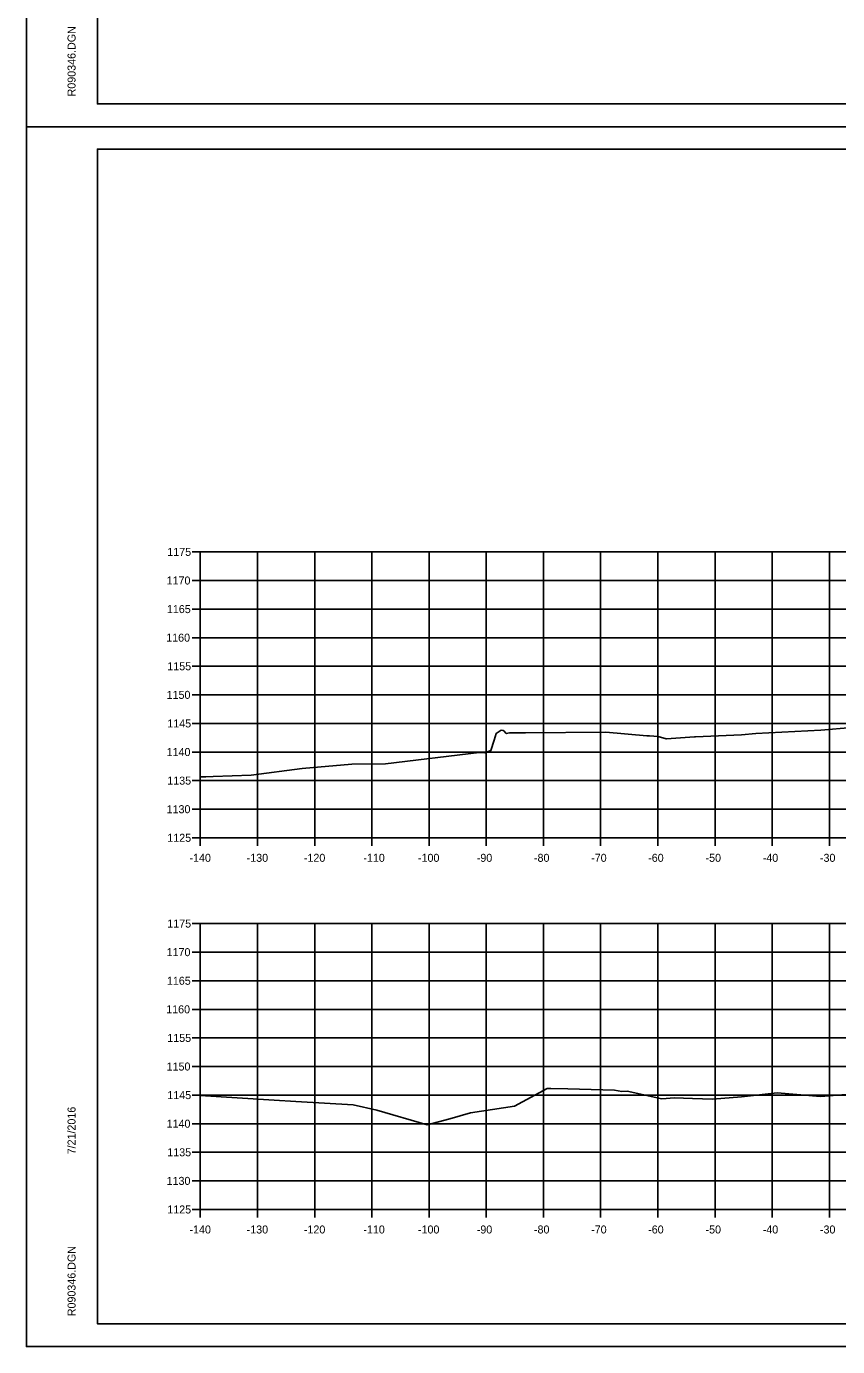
# Model space of a CAD drawing. Extents: x 1368971 to 1374497, y 378717 to 381839.
# Drawn here: x 1371092.2 to 1371234.1, y 381199.4 to 381430.3 of the extents above; entities that cross this region are included whole.
import ezdxf

# ---------------------------------------------------------------- set-up
doc = ezdxf.new("R2010")
doc.units = 0
for name, color, linetype in [('R_Axis', 7, 'Continuous'), ('R_Axis Annot', 7, 'Continuous'), ('R_Exist Surface', 7, 'Continuous'), ('R_Grid', 7, 'Continuous'), ('R_No Plot', 7, 'Continuous')]:
    doc.layers.add(name, color=color, linetype=linetype)

msp = doc.modelspace()

# ---------------------------------------------------------------- linework, layer by layer
at = {"layer": 'R_Axis'}
for p, q in [((1371121.24, 381338.41), (1371122.64, 381338.41)), ((1371122.64, 381288.41), (1371122.64, 381338.41)), ((1371121.24, 381333.41), (1371122.64, 381333.41)), ((1371121.24, 381328.41), (1371122.64, 381328.41)), ((1371121.24, 381323.41), (1371122.64, 381323.41)), ((1371121.24, 381318.41), (1371122.64, 381318.41)), ((1371121.24, 381313.41), (1371122.64, 381313.41)), ((1371121.24, 381308.41), (1371122.64, 381308.41)), ((1371121.24, 381303.41), (1371122.64, 381303.41)), ((1371121.24, 381298.41), (1371122.64, 381298.41)), ((1371121.24, 381293.41), (1371122.64, 381293.41)), ((1371121.24, 381288.41), (1371122.64, 381288.41)), ((1371122.64, 381288.41), (1371402.64, 381288.41)), ((1371122.64, 381287.01), (1371122.64, 381288.41)), ((1371132.64, 381287.01), (1371132.64, 381288.41)), ((1371142.64, 381287.01), (1371142.64, 381288.41)), ((1371152.64, 381287.01), (1371152.64, 381288.41)), ((1371162.64, 381287.01), (1371162.64, 381288.41)), ((1371172.64, 381287.01), (1371172.64, 381288.41)), ((1371182.64, 381287.01), (1371182.64, 381288.41)), ((1371192.64, 381287.01), (1371192.64, 381288.41)), ((1371202.64, 381287.01), (1371202.64, 381288.41)), ((1371212.64, 381287.01), (1371212.64, 381288.41)), ((1371222.64, 381287.01), (1371222.64, 381288.41)), ((1371232.64, 381287.01), (1371232.64, 381288.41)), ((1371121.24, 381273.41), (1371122.64, 381273.41)), ((1371122.64, 381223.41), (1371122.64, 381273.41)), ((1371121.24, 381268.41), (1371122.64, 381268.41)), ((1371121.24, 381263.41), (1371122.64, 381263.41)), ((1371121.24, 381258.41), (1371122.64, 381258.41)), ((1371121.24, 381253.41), (1371122.64, 381253.41)), ((1371121.24, 381248.41), (1371122.64, 381248.41)), ((1371121.24, 381243.41), (1371122.64, 381243.41)), ((1371121.24, 381238.41), (1371122.64, 381238.41)), ((1371121.24, 381233.41), (1371122.64, 381233.41)), ((1371121.24, 381228.41), (1371122.64, 381228.41)), ((1371121.24, 381223.41), (1371122.64, 381223.41)), ((1371122.64, 381223.41), (1371402.64, 381223.41)), ((1371122.64, 381222.01), (1371122.64, 381223.41)), ((1371132.64, 381222.01), (1371132.64, 381223.41)), ((1371142.64, 381222.01), (1371142.64, 381223.41)), ((1371152.64, 381222.01), (1371152.64, 381223.41)), ((1371162.64, 381222.01), (1371162.64, 381223.41)), ((1371172.64, 381222.01), (1371172.64, 381223.41)), ((1371182.64, 381222.01), (1371182.64, 381223.41)), ((1371192.64, 381222.01), (1371192.64, 381223.41)), ((1371202.64, 381222.01), (1371202.64, 381223.41)), ((1371212.64, 381222.01), (1371212.64, 381223.41)), ((1371222.64, 381222.01), (1371222.64, 381223.41)), ((1371232.64, 381222.01), (1371232.64, 381223.41))]:
    msp.add_line(p, q, dxfattribs=at)
at = {"layer": 'R_Exist Surface'}
for points in [[(1371122.64, 381299.05), (1371123.59, 381299.09), (1371124.87, 381299.14), (1371131.55, 381299.39), (1371140.46, 381300.53), (1371149.14, 381301.31), (1371155, 381301.33), (1371171.42, 381303.33), (1371172.41, 381303.28), (1371173.41, 381303.67), (1371174.04, 381305.49), (1371174.39, 381306.65), (1371175.22, 381307.26), (1371175.59, 381307.2), (1371175.7, 381307.11), (1371176.12, 381306.63), (1371176.71, 381306.76), (1371179.52, 381306.78), (1371193.57, 381306.87), (1371200.7, 381306.24), (1371201.2, 381306.23), (1371202.68, 381306.1), (1371204.07, 381305.69), (1371204.13, 381305.73), (1371209.05, 381306.07), (1371209.22, 381306.09), (1371217.24, 381306.42), (1371219.79, 381306.64), (1371231.16, 381307.24), (1371236.57, 381307.71)], [(1371122.64, 381243.36), (1371135.55, 381242.55), (1371139.35, 381242.27), (1371149.36, 381241.69), (1371153.48, 381240.77), (1371162.29, 381238.19), (1371166.24, 381239.29), (1371169.87, 381240.31), (1371177.6, 381241.45), (1371183.28, 381244.55), (1371183.93, 381244.57), (1371186.91, 381244.52), (1371195.05, 381244.28), (1371196.32, 381244.05), (1371197.26, 381244.08), (1371203.34, 381242.76), (1371205.55, 381242.93), (1371208.67, 381242.79), (1371212.17, 381242.71), (1371217.24, 381243.11), (1371223.51, 381243.79), (1371231.05, 381243.19), (1371235.54, 381243.53)]]:
    msp.add_lwpolyline(points, dxfattribs=at)
at = {"layer": 'R_Grid'}
for p, q in [((1371122.64, 381338.41), (1371402.64, 381338.41)), ((1371122.64, 381288.41), (1371122.64, 381338.41)), ((1371132.64, 381288.41), (1371132.64, 381338.41)), ((1371142.64, 381288.41), (1371142.64, 381338.41)), ((1371152.64, 381288.41), (1371152.64, 381338.41)), ((1371162.64, 381288.41), (1371162.64, 381338.41)), ((1371172.64, 381288.41), (1371172.64, 381338.41)), ((1371182.64, 381288.41), (1371182.64, 381338.41)), ((1371192.64, 381288.41), (1371192.64, 381338.41)), ((1371202.64, 381288.41), (1371202.64, 381338.41)), ((1371212.64, 381288.41), (1371212.64, 381338.41)), ((1371222.64, 381288.41), (1371222.64, 381338.41)), ((1371232.64, 381288.41), (1371232.64, 381338.41)), ((1371122.64, 381333.41), (1371402.64, 381333.41)), ((1371122.64, 381328.41), (1371402.64, 381328.41)), ((1371122.64, 381323.41), (1371402.64, 381323.41)), ((1371122.64, 381318.41), (1371402.64, 381318.41)), ((1371122.64, 381313.41), (1371402.64, 381313.41)), ((1371122.64, 381308.41), (1371402.64, 381308.41)), ((1371122.64, 381303.41), (1371402.64, 381303.41)), ((1371122.64, 381298.41), (1371402.64, 381298.41)), ((1371122.64, 381293.41), (1371402.64, 381293.41)), ((1371122.64, 381288.41), (1371402.64, 381288.41)), ((1371122.64, 381273.41), (1371402.64, 381273.41)), ((1371122.64, 381223.41), (1371122.64, 381273.41)), ((1371132.64, 381223.41), (1371132.64, 381273.41)), ((1371142.64, 381223.41), (1371142.64, 381273.41)), ((1371152.64, 381223.41), (1371152.64, 381273.41)), ((1371162.64, 381223.41), (1371162.64, 381273.41)), ((1371172.64, 381223.41), (1371172.64, 381273.41)), ((1371182.64, 381223.41), (1371182.64, 381273.41)), ((1371192.64, 381223.41), (1371192.64, 381273.41)), ((1371202.64, 381223.41), (1371202.64, 381273.41)), ((1371212.64, 381223.41), (1371212.64, 381273.41)), ((1371222.64, 381223.41), (1371222.64, 381273.41)), ((1371232.64, 381223.41), (1371232.64, 381273.41)), ((1371122.64, 381268.41), (1371402.64, 381268.41)), ((1371122.64, 381263.41), (1371402.64, 381263.41)), ((1371122.64, 381258.41), (1371402.64, 381258.41)), ((1371122.64, 381253.41), (1371402.64, 381253.41)), ((1371122.64, 381248.41), (1371402.64, 381248.41)), ((1371122.64, 381243.41), (1371402.64, 381243.41)), ((1371122.64, 381238.41), (1371402.64, 381238.41)), ((1371122.64, 381233.41), (1371402.64, 381233.41)), ((1371122.64, 381228.41), (1371402.64, 381228.41)), ((1371122.64, 381223.41), (1371402.64, 381223.41))]:
    msp.add_line(p, q, dxfattribs=at)
at = {"layer": 'R_No Plot'}
for p, q in [((1371104.64, 381416.75), (1371104.64, 381622.21)), ((1371104.64, 381416.75), (1371104.64, 381416.75)), ((1371420.82, 381416.75), (1371104.64, 381416.75)), ((1371092.24, 381412.77), (1371425.58, 381412.77)), ((1371092.24, 381412.77), (1371425.58, 381412.77)), ((1371104.64, 381408.87), (1371420.82, 381408.87)), ((1371104.64, 381203.41), (1371104.64, 381408.87)), ((1371104.64, 381203.41), (1371104.64, 381203.41)), ((1371420.82, 381203.41), (1371104.64, 381203.41)), ((1371092.24, 381199.43), (1371425.58, 381199.43))]:
    msp.add_line(p, q, dxfattribs=at)
for points in [[(1371092.24, 381626.1), (1371425.58, 381626.1), (1371425.58, 381412.77), (1371092.24, 381412.77)], [(1371338.56, 381622.21), (1371338.56, 381612.33), (1371374.3, 381612.33), (1371374.3, 381609.41), (1371397.49, 381609.41), (1371397.49, 381586.19), (1371420.82, 381586.19), (1371420.82, 381416.75), (1371104.64, 381416.75), (1371104.64, 381622.21)], [(1371092.24, 381412.77), (1371425.58, 381412.77), (1371425.58, 381199.43), (1371092.24, 381199.43)], [(1371338.56, 381408.87), (1371338.56, 381398.99), (1371374.3, 381398.99), (1371374.3, 381396.07), (1371397.49, 381396.07), (1371397.49, 381372.86), (1371420.82, 381372.86), (1371420.82, 381203.41), (1371104.64, 381203.41), (1371104.64, 381408.87)]]:
    msp.add_lwpolyline(points, close=True, dxfattribs=at)

# ---------------------------------------------------------------- texts
at = {"layer": 'R_Axis'}
for p in [(1371122.64, 381288.41), (1371122.64, 381223.41)]:
    msp.add_text('-', height=0.0001, dxfattribs=at).set_placement(p)
at = {"layer": 'R_Axis Annot'}
for s, p in [('1175', (1371116.87, 381337.71)), ('1170', (1371116.75, 381332.71)), ('1165', (1371116.8, 381327.71)), ('1160', (1371116.68, 381322.71)), ('1155', (1371116.87, 381317.71)), ('1150', (1371116.75, 381312.71)), ('1145', (1371116.87, 381307.71)), ('1140', (1371116.75, 381302.71)), ('1135', (1371116.87, 381297.71)), ('1130', (1371116.75, 381292.71)), ('1125', (1371116.87, 381287.71)), ('-140', (1371120.75, 381284.21)), ('-130', (1371130.75, 381284.21)), ('-120', (1371140.75, 381284.21)), ('-110', (1371151.15, 381284.21)), ('-100', (1371160.7, 381284.21)), ('-90', (1371170.98, 381284.21)), ('-80', (1371180.98, 381284.21)), ('-70', (1371190.98, 381284.21)), ('-60', (1371200.95, 381284.21)), ('-50', (1371210.98, 381284.21)), ('-40', (1371220.98, 381284.21)), ('-30', (1371230.98, 381284.21)), ('1175', (1371116.87, 381272.71)), ('1170', (1371116.75, 381267.71)), ('1165', (1371116.8, 381262.71)), ('1160', (1371116.68, 381257.71)), ('1155', (1371116.87, 381252.71)), ('1150', (1371116.75, 381247.71)), ('1145', (1371116.87, 381242.71)), ('1140', (1371116.75, 381237.71)), ('1135', (1371116.87, 381232.71)), ('1130', (1371116.75, 381227.71)), ('1125', (1371116.87, 381222.71)), ('-140', (1371120.75, 381219.21)), ('-130', (1371130.75, 381219.21)), ('-120', (1371140.75, 381219.21)), ('-110', (1371151.15, 381219.21)), ('-100', (1371160.7, 381219.21)), ('-90', (1371170.98, 381219.21)), ('-80', (1371180.98, 381219.21)), ('-70', (1371190.98, 381219.21)), ('-60', (1371200.95, 381219.21)), ('-50', (1371210.98, 381219.21)), ('-40', (1371220.98, 381219.21)), ('-30', (1371230.98, 381219.21))]:
    msp.add_text(s, height=1.4, dxfattribs=at).set_placement(p)
at = {"layer": 'R_No Plot'}
for s, p in [('R090346.DGN', (1371100.83, 381418.07)), ('7/21/2016', (1371100.83, 381233.05)), ('R090346.DGN', (1371100.83, 381204.74))]:
    msp.add_text(s, height=1.4, rotation=90, dxfattribs=at).set_placement(p)

doc.saveas('drawing.dxf')
